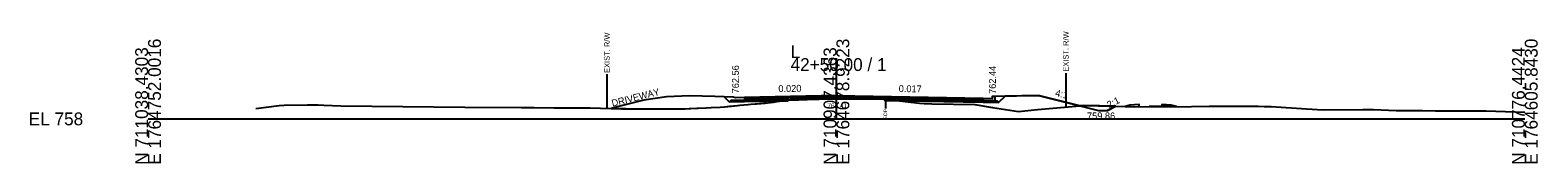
# Model space of a CAD drawing. Extents: x -26 to 5303, y -10 to 9578.
# Drawn here: x 2974.3 to 3302.8, y 2490.3 to 2518.8 of the extents above; entities that cross this region are included whole.
import ezdxf

# ---------------------------------------------------------------- set-up
doc = ezdxf.new("R2010")
doc.units = 0
for name, color, linetype in [('Default', 7, 'Continuous'), ('Exist CMT Pavement', 7, 'Continuous'), ('Exist Cross Section Cell', 7, 'Continuous'), ('Exist XS Ground Line', 7, 'Continuous'), ('Old_Level_10', 7, 'Continuous'), ('Old_Level_3', 7, 'Continuous'), ('Prop CMT Conc Surface', 7, 'Continuous'), ('Prop CMT Concrete Structures', 7, 'Continuous'), ('Prop CMT Pvmt Course 1', 7, 'Continuous'), ('Prop CMT Pvmt Course 1 CG', 7, 'Continuous'), ('Prop CMT Pvmt Course 2', 7, 'Continuous'), ('Prop CMT Pvmt Course 3', 7, 'Continuous'), ('Prop CMT Pvmt Surface', 7, 'Continuous'), ('Prop CMT Slope Grass', 7, 'Continuous'), ('Prop CMT Subgrade Earthwork', 7, 'Continuous'), ('Prop XS DDE', 7, 'Continuous'), ('Prop XS DDE Earthwork Shape', 7, 'Continuous'), ('Prop XS Earthwork Shape', 7, 'Continuous'), ('Prop XS Hydro Elevations', 7, 'Continuous'), ('Prop XS Hydro Slope Text', 7, 'Continuous'), ('Prop XS SE Text', 7, 'Continuous'), ('Prop XS Side Slope Text', 7, 'Continuous'), ('Prop XS Wedging', 7, 'Continuous')]:
    doc.layers.add(name, color=color, linetype=linetype)

msp = doc.modelspace()

# ---------------------------------------------------------------- linework, layer by layer
at = {"layer": 'Exist CMT Pavement'}
msp.add_lwpolyline([(3139.47, 2504.11), (3139.95, 2504.13), (3140.4, 2504.14), (3141.81, 2504.18), (3142.77, 2504.21), (3143.65, 2504.24), (3145.63, 2504.29), (3146.15, 2504.31), (3148.58, 2504.38), (3149.52, 2504.41), (3149.9, 2504.41), (3150.91, 2504.41), (3151.36, 2504.41), (3152.63, 2504.4), (3154.22, 2504.39), (3154.67, 2504.39), (3155.49, 2504.39), (3156.51, 2504.4), (3157.08, 2504.39), (3158.35, 2504.38), (3160.12, 2504.36), (3160.58, 2504.32)], dxfattribs=at)
at = {"layer": 'Exist Cross Section Cell'}
for p, q in [((3150, 2500), (3150, 2513.24)), ((3000, 2500), (3150, 2500)), ((3150, 2500), (3300, 2500))]:
    msp.add_line(p, q, dxfattribs=at)
at = {"layer": 'Exist XS Ground Line'}
msp.add_lwpolyline([(3023.47, 2502.29), (3028.59, 2502.93), (3029.69, 2503.02), (3034.74, 2503.05), (3037.04, 2503.08), (3038.32, 2503.03), (3042.02, 2502.84), (3069.02, 2502.59), (3081.27, 2502.46), (3084.13, 2502.47), (3088.5, 2502.39), (3095.85, 2502.39), (3096.32, 2502.38), (3103.2, 2502.17), (3107.04, 2502.22), (3112.62, 2502.23), (3115.33, 2502.2), (3116.08, 2502.22), (3117.01, 2502.23), (3117.92, 2502.24), (3119.87, 2502.32), (3121.6, 2502.4), (3122.73, 2502.46), (3124.7, 2502.58), (3125.59, 2502.64), (3127.11, 2502.79), (3128.46, 2502.92), (3128.95, 2502.96), (3129.83, 2503.05), (3130.79, 2503.14), (3131.32, 2503.2), (3132.62, 2503.32), (3134.46, 2503.44), (3134.96, 2503.5), (3136.3, 2503.65), (3137.04, 2503.76), (3138.14, 2503.92), (3138.92, 2504.03), (3139.47, 2504.11), (3139.95, 2504.13), (3140.4, 2504.14), (3141.81, 2504.18), (3142.77, 2504.21), (3143.65, 2504.24), (3145.22, 2504.28), (3145.63, 2504.29), (3147.32, 2504.35), (3148.58, 2504.38), (3149.52, 2504.41), (3149.9, 2504.41), (3150.91, 2504.41), (3151.36, 2504.41), (3152.84, 2504.39), (3154.22, 2504.39), (3154.67, 2504.39), (3155.49, 2504.39), (3157.08, 2504.39), (3158.35, 2504.38), (3160.12, 2504.36), (3160.66, 2504.31), (3168.13, 2503.41), (3169.09, 2503.34), (3170.79, 2503.28), (3180.14, 2503.16), (3183.98, 2502.51), (3189.68, 2501.65), (3193.79, 2502.05), (3203.86, 2502.93), (3213.47, 2502.71), (3214.16, 2502.71), (3214.86, 2502.66), (3227.36, 2502.71), (3231.21, 2502.75), (3241.87, 2502.75), (3243.22, 2502.73), (3244.71, 2502.68), (3252.42, 2502.19), (3256.09, 2501.98), (3264.7, 2502.02), (3267.03, 2502.05), (3271.94, 2501.86), (3277.72, 2501.83), (3280.53, 2501.78), (3288.48, 2501.77), (3291.57, 2501.79), (3300, 2501.5)], dxfattribs=at)
at = {"layer": 'Old_Level_10'}
for p, q in [((3200, 2510), (3200, 2502.59)), ((3100, 2509.72), (3100, 2502.32)), ((3160.66, 2504.31), (3160.66, 2502.26))]:
    msp.add_line(p, q, dxfattribs=at)
at = {"layer": 'Prop CMT Conc Surface'}
for points in [[(3130, 2504.68), (3128, 2504.56)], [(3182, 2504.55), (3184, 2504.44)], [(3184, 2504.44), (3184, 2504.94), (3184.5, 2504.94)]]:
    msp.add_lwpolyline(points, dxfattribs=at)
at = {"layer": 'Prop CMT Concrete Structures'}
for points in [[(3182, 2504.55), (3184, 2504.44), (3184, 2504.94), (3184.5, 2504.94)], [(3184.5, 2504.94), (3184.5, 2503.93), (3182, 2503.97)], [(3182, 2503.97), (3182, 2504.55)]]:
    msp.add_lwpolyline(points, dxfattribs=at)
at = {"layer": 'Prop CMT Pvmt Course 1'}
for points in [[(3150, 2505.08), (3130, 2504.68)], [(3130, 2504.43), (3139.47, 2504.62)], [(3139.47, 2504.62), (3150, 2504.83)], [(3139.47, 2504.62), (3139.47, 2504.62)], [(3150, 2504.83), (3150, 2505.08)], [(3150, 2505.08), (3182, 2504.55)], [(3150, 2504.83), (3150, 2504.83), (3150, 2504.83)], [(3160.58, 2504.66), (3150, 2504.83)], [(3182, 2504.3), (3160.58, 2504.66)], [(3160.58, 2504.66), (3160.58, 2504.66)], [(3182, 2504.55), (3182, 2504.3)]]:
    msp.add_lwpolyline(points, dxfattribs=at)
at = {"layer": 'Prop CMT Pvmt Course 1 CG'}
for points in [[(3130, 2504.1), (3127, 2504.04), (3126.66, 2503.7)], [(3126.66, 2503.7), (3130, 2503.77)], [(3130, 2503.77), (3130, 2504.1)], [(3182, 2503.97), (3185, 2503.92), (3185.34, 2503.58)], [(3182, 2503.64), (3182, 2503.97)], [(3185.34, 2503.58), (3182, 2503.64)]]:
    msp.add_lwpolyline(points, dxfattribs=at)
at = {"layer": 'Prop CMT Pvmt Course 2'}
for points in [[(3139.47, 2504.62), (3130, 2504.43)], [(3130, 2504.43), (3130, 2504.1)], [(3130, 2504.1), (3139.47, 2504.29)], [(3139.47, 2504.29), (3139.47, 2504.62)], [(3160.58, 2504.32), (3160.58, 2504.66)], [(3160.58, 2504.66), (3182, 2504.3)], [(3182, 2503.97), (3160.58, 2504.32)], [(3182, 2504.3), (3182, 2503.97)]]:
    msp.add_lwpolyline(points, dxfattribs=at)
at = {"layer": 'Prop CMT Pvmt Course 3'}
for points in [[(3139.47, 2504.29), (3130, 2504.1)], [(3130, 2504.1), (3130, 2503.77)], [(3130, 2503.77), (3139.47, 2503.96)], [(3139.47, 2503.96), (3139.47, 2504.29)], [(3160.58, 2504.32), (3182, 2503.97)], [(3160.58, 2503.99), (3160.58, 2504.32)], [(3182, 2503.64), (3160.58, 2503.99)], [(3182, 2503.97), (3182, 2503.64)]]:
    msp.add_lwpolyline(points, dxfattribs=at)
at = {"layer": 'Prop CMT Pvmt Surface'}
for p, q in [((3108, 2504.05), (3101.04, 2502.31)), ((3113, 2504.8), (3108, 2504.05)), ((3118, 2505), (3113, 2504.8)), ((3123.5, 2504.89), (3118, 2505)), ((3127.5, 2504.73), (3123.5, 2504.89)), ((3128, 2504.56), (3127.5, 2504.73)), ((3130, 2504.68), (3128, 2504.56))]:
    msp.add_line(p, q, dxfattribs=at)
for points in [[(3150, 2505.08), (3130, 2504.68)], [(3150, 2505.08), (3182, 2504.55)]]:
    msp.add_lwpolyline(points, dxfattribs=at)
at = {"layer": 'Prop CMT Slope Grass'}
msp.add_lwpolyline([(3184.5, 2504.94), (3194, 2505.13), (3203.07, 2502.86)], dxfattribs=at)
at = {"layer": 'Prop CMT Subgrade Earthwork'}
for p, q in [((3139.47, 2503.96), (3139.47, 2504.11)), ((3160.58, 2503.99), (3160.58, 2504.32))]:
    msp.add_line(p, q, dxfattribs=at)
for points in [[(3130, 2503.77), (3126.66, 2503.7), (3125.55, 2504.81)], [(3139.47, 2503.96), (3130, 2503.77)], [(3160.58, 2503.99), (3182, 2503.64)], [(3182, 2503.64), (3185.34, 2503.58), (3186.74, 2504.98)]]:
    msp.add_lwpolyline(points, dxfattribs=at)
at = {"layer": 'Prop XS DDE'}
for p, q in [((3203.07, 2502.86), (3207.08, 2501.86)), ((3207.08, 2501.86), (3209.08, 2501.86)), ((3210.9, 2502.77), (3209.08, 2501.86))]:
    msp.add_line(p, q, dxfattribs=at)
msp.add_lwpolyline([(3203.07, 2502.86), (3207.08, 2501.86), (3209.08, 2501.86), (3210.9, 2502.77)], dxfattribs=at)
at = {"layer": 'Prop XS DDE Earthwork Shape'}
for p, q in [((3203.86, 2502.93), (3203.07, 2502.86)), ((3210.9, 2502.77), (3203.86, 2502.93)), ((3209.08, 2501.86), (3210.9, 2502.77))]:
    msp.add_line(p, q, dxfattribs=at)
msp.add_lwpolyline([(3203.07, 2502.86), (3207.08, 2501.86), (3209.08, 2501.86)], dxfattribs=at)
at = {"layer": 'Prop XS Earthwork Shape'}
for points in [[(3131.32, 2503.2), (3133.2, 2503.34), (3134.18, 2503.42), (3134.96, 2503.5), (3136.3, 2503.65), (3137.04, 2503.76), (3138.14, 2503.92), (3138.19, 2503.93), (3130, 2503.77), (3126.66, 2503.7), (3125.55, 2504.81), (3123.5, 2504.89), (3118, 2505), (3113, 2504.8), (3108, 2504.05), (3101.04, 2502.31), (3107.04, 2502.22), (3112.62, 2502.23), (3115.33, 2502.2), (3116.08, 2502.22), (3117.01, 2502.23), (3119.57, 2502.31), (3119.87, 2502.32), (3121.6, 2502.4), (3122.73, 2502.46), (3124.7, 2502.58), (3125.59, 2502.64), (3126.73, 2502.75), (3128.46, 2502.92), (3128.95, 2502.96), (3129.83, 2503.05), (3130.79, 2503.14)], [(3137.04, 2503.76), (3138.14, 2503.92), (3138.19, 2503.93), (3130, 2503.77), (3126.66, 2503.7), (3125.55, 2504.81), (3123.5, 2504.89), (3118, 2505), (3113, 2504.8), (3108, 2504.05), (3101.04, 2502.31), (3107.04, 2502.22), (3112.62, 2502.23), (3115.33, 2502.2), (3116.08, 2502.22), (3117.01, 2502.23), (3119.57, 2502.31), (3119.87, 2502.32), (3121.6, 2502.4), (3122.73, 2502.46), (3124.7, 2502.58), (3125.59, 2502.64), (3126.73, 2502.75), (3128.46, 2502.92), (3128.95, 2502.96), (3129.83, 2503.05), (3130.79, 2503.14), (3131.32, 2503.2), (3133.2, 2503.34), (3134.18, 2503.42), (3134.96, 2503.5), (3136.3, 2503.65)], [(3139.47, 2503.96), (3138.19, 2503.93), (3138.92, 2504.03), (3139.47, 2504.11)], [(3160.58, 2503.99), (3163.77, 2503.94), (3160.66, 2504.31), (3160.58, 2504.32)], [(3160.58, 2504.32), (3160.66, 2504.31), (3163.77, 2503.94), (3160.58, 2503.99)], [(3168.13, 2503.41), (3169.09, 2503.34), (3170.79, 2503.28), (3180.14, 2503.16), (3183.98, 2502.51), (3189.68, 2501.65), (3193.79, 2502.05), (3203.07, 2502.86), (3194, 2505.13), (3186.74, 2504.98), (3185.34, 2503.58), (3182, 2503.64), (3163.77, 2503.94)], [(3180.14, 2503.16), (3183.98, 2502.51), (3189.68, 2501.65), (3193.79, 2502.05), (3203.07, 2502.86), (3194, 2505.13), (3186.74, 2504.98), (3185.34, 2503.58), (3182, 2503.64), (3163.77, 2503.94), (3168.13, 2503.41), (3169.09, 2503.34), (3170.79, 2503.28)], [(3212.9, 2502.73), (3213.47, 2502.71), (3214.16, 2502.71), (3214.86, 2502.66), (3215.94, 2502.67), (3215.94, 2503.17), (3213.94, 2502.99)], [(3215.94, 2502.67), (3215.94, 2503.17), (3213.94, 2502.99), (3212.9, 2502.73), (3213.47, 2502.71), (3214.16, 2502.71), (3214.86, 2502.66)], [(3218.12, 2502.67), (3220.96, 2502.69), (3220.96, 2502.67)], [(3220.96, 2502.69), (3224.1, 2502.7), (3222.96, 2502.99), (3220.96, 2503.17)], [(3222.96, 2502.99), (3224.1, 2502.7), (3220.96, 2502.69), (3220.96, 2503.17)]]:
    msp.add_lwpolyline(points, close=True, dxfattribs=at)
at = {"layer": 'Prop XS Wedging'}
msp.add_lwpolyline([(3139.47, 2504.11), (3139.47, 2504.62), (3139.95, 2504.63), (3140.4, 2504.64), (3141.81, 2504.67), (3142.77, 2504.69), (3143.65, 2504.7), (3145.63, 2504.74), (3146.15, 2504.76), (3148.58, 2504.8), (3149.52, 2504.82), (3149.89, 2504.83), (3150, 2504.83), (3150.91, 2504.81), (3151.36, 2504.8), (3152.63, 2504.78), (3154.22, 2504.75), (3154.67, 2504.74), (3155.49, 2504.72), (3156.51, 2504.7), (3157.08, 2504.69), (3158.35, 2504.67), (3160.12, 2504.63), (3160.66, 2504.62), (3160.66, 2504.31), (3160.12, 2504.36), (3158.35, 2504.38), (3157.08, 2504.39), (3156.51, 2504.4), (3155.49, 2504.39), (3154.67, 2504.39), (3154.22, 2504.39), (3152.63, 2504.4), (3151.36, 2504.41), (3150.91, 2504.41), (3150, 2504.41), (3149.89, 2504.41), (3149.52, 2504.41), (3148.58, 2504.38), (3146.15, 2504.31), (3145.63, 2504.29), (3143.65, 2504.24), (3142.77, 2504.21), (3141.81, 2504.18), (3140.4, 2504.14), (3139.95, 2504.13)], close=True, dxfattribs=at)

# ---------------------------------------------------------------- texts
at = {"layer": 'Default'}
msp.add_text('-', height=0.0001, dxfattribs=at).set_placement((3000, 2500))
at = {"layer": 'Exist Cross Section Cell'}
for s, p in [('E 1764752.0016', (3002.8, 2490)), ('E 1764678.9223', (3152.8, 2490)), ('E 1764605.8430', (3302.8, 2490)), ('N 711038.4303', (3000, 2490)), ('N 710907.4363', (3150, 2490)), ('N 710776.4424', (3300, 2490))]:
    msp.add_text(s, height=2.8, rotation=90, dxfattribs=at).set_placement(p)
for s, p in [('42+50.00 / 1', (3140, 2510.44)), ('L', (3140, 2513.24)), ('EL 758', (2974, 2498.6))]:
    msp.add_text(s, height=2.8, dxfattribs=at).set_placement(p)
at = {"layer": 'Old_Level_10'}
for s, height, p in [('EXIST. R/W', 1.181, (3100.59, 2510.03)), ('EXIST. R/W', 1.181, (3200.59, 2510.3)), ('EOP', 0.787, (3161.05, 2499.86))]:
    msp.add_text(s, height=height, rotation=90, dxfattribs=at).set_placement(p)
at = {"layer": 'Old_Level_3'}
msp.add_text('762.41', height=1, dxfattribs=at).set_placement((3148.05, 2502.41))
at = {"layer": 'Prop XS Hydro Elevations'}
for s, p in [('762.56', (3128.75, 2505.56)), ('762.44', (3184.75, 2505.44))]:
    msp.add_text(s, height=1.5, rotation=90, dxfattribs=at).set_placement(p)
at = {"layer": 'Prop XS Hydro Slope Text'}
msp.add_text('759.86', height=1.5, dxfattribs=at).set_placement((3204.6, 2499.91))
at = {"layer": 'Prop XS SE Text'}
for s, rotation, p in [('0.020', 1.1458, (3137.36, 2505.83)), ('0.017', 359.0513, (3163.56, 2505.86))]:
    msp.add_text(s, height=1.5, rotation=rotation, dxfattribs=at).set_placement(p)
at = {"layer": 'Prop XS Side Slope Text'}
for s, rotation, p in [('DRIVEWAY', 14.0362, (3101.21, 2502.66)), ('4:1', 345.9638, (3197.56, 2505.01)), ('2:1', 26.5651, (3209.41, 2502.3))]:
    msp.add_text(s, height=1.5, rotation=rotation, dxfattribs=at).set_placement(p)

doc.saveas('drawing.dxf')
